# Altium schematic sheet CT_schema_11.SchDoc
size 382 x 278 mm
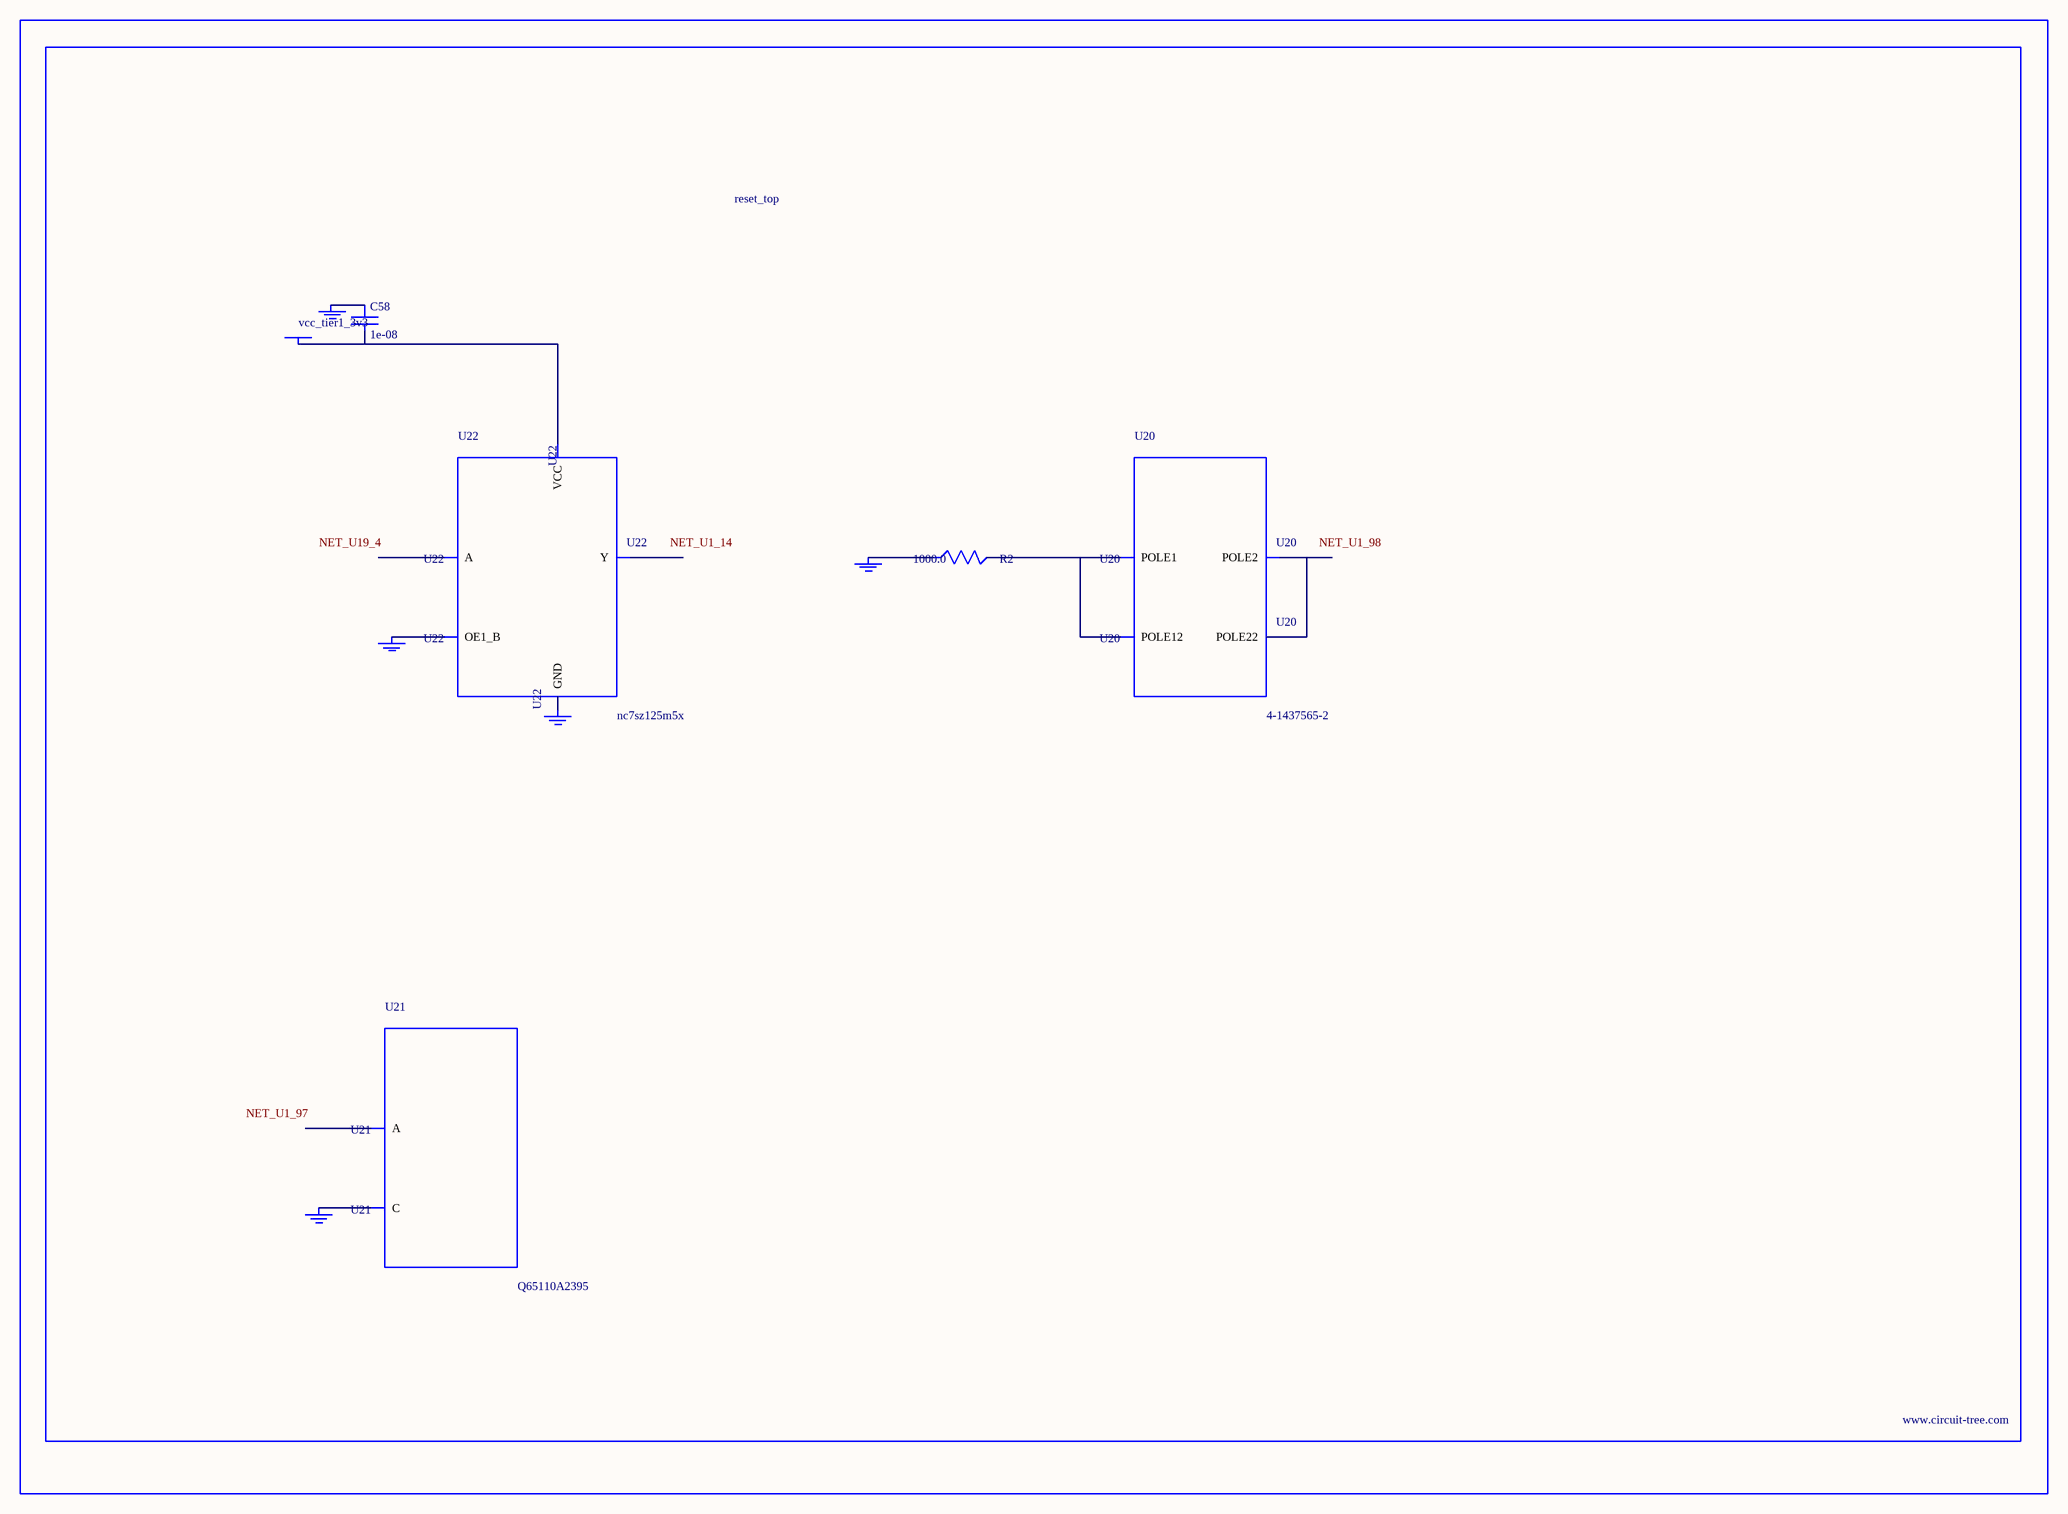
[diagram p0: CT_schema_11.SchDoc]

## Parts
BORDER10  (no value)
C58  1e-08  [C0402]
GND_INSTANCE_10_0  (no value)
GND_INSTANCE_10_1  (no value)
GND_INSTANCE_10_2  (no value)
GND_INSTANCE_10_3  (no value)
GND_INSTANCE_10_4  (no value)
POWER_INSTANCE_10_0  vcc_tier1_3v3
R2  1000.0  [R0603]
U20  4-1437565-2  [SW_4-1437565-2]
U21  Q65110A2395  [LGM67K-G1J2-24-Z]
U22  nc7sz125m5x  [NC7SZ125M5X]

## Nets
NetC58_1: C58.1 GND_INSTANCE_10_2.0(GND)
NetC58_2: C58.2 POWER_INSTANCE_10_0.0(PWR) U22.5(VCC)
NetGND_INSTANCE_10_0_0: GND_INSTANCE_10_0.0(GND) R2.1
NetGND_INSTANCE_10_1_0: GND_INSTANCE_10_1.0(GND) U21.C
NetGND_INSTANCE_10_3_0: GND_INSTANCE_10_3.0(GND) U22.1(OE1_B)
NetGND_INSTANCE_10_4_0: GND_INSTANCE_10_4.0(GND) U22.3(GND)
NetR2_2: R2.2 U20.1(POLE1) U20.2(POLE12)
NetU20_3: U20.3(POLE2) U20.4(POLE22)

Not connected (* = marked no-connect by the designer): U21 A; U22 2(A) 4(Y)

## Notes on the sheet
- Labels drawn without touching a wire or pin: NET_U1_14, NET_U1_97, NET_U1_98, NET_U19_4

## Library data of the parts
BORDER10 = BORDER_PAGE10
C58 = C0402C103K3RAC
GND_INSTANCE_10_0-GND_INSTANCE_10_4 = GND
POWER_INSTANCE_10_0 = PWR
R2 = RC0603JR-071KL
